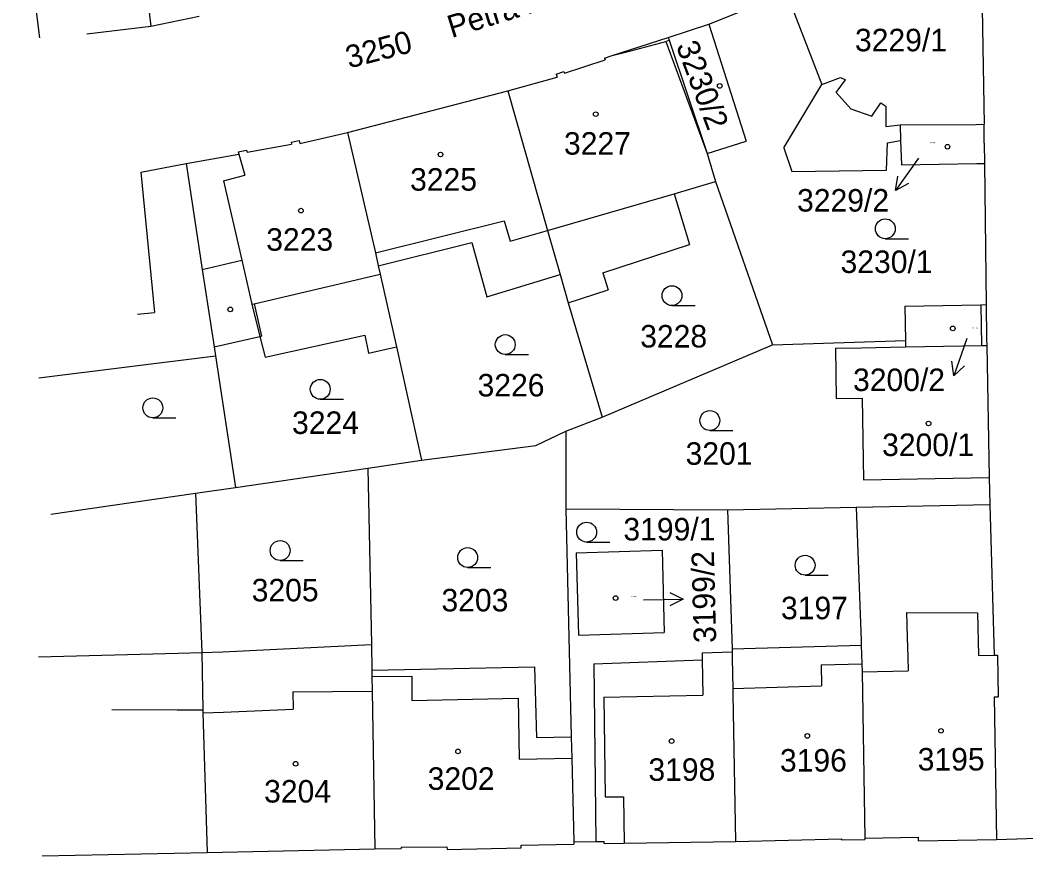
# Model space of a CAD drawing. Extents: x -735092 to -733385, y -1122435 to -1118992.
# Drawn here: x -734521.9 to -734445.9, y -1120334.2 to -1120271.1 of the extents above; entities that cross this region are included whole.
import ezdxf

# ---------------------------------------------------------------- set-up
doc = ezdxf.new("R2010")
doc.units = 0
for name, color, linetype in [('Vrstva 1', 7, 'Continuous'), ('Vrstva 15', 7, 'Continuous'), ('Vrstva 16', 7, 'Continuous'), ('Vrstva 18', 7, 'Continuous'), ('Vrstva 19', 7, 'Continuous'), ('Vrstva 25', 7, 'Continuous'), ('Vrstva 4', 7, 'Continuous')]:
    doc.layers.add(name, color=color, linetype=linetype)

msp = doc.modelspace()

# ---------------------------------------------------------------- linework, layer by layer
at = {"layer": 'Vrstva 1'}
for points in [[(-734521.87, -1120260.86), (-734520.4, -1120272.42)], [(-734449.23, -1120267.25), (-734449.01, -1120278.95)], [(-734469.82, -1120271.38), (-734463.95, -1120269.02)], [(-734463.95, -1120269.02), (-734461.29, -1120275.96)], [(-734512, -1120271.55), (-734508.33, -1120270.79)], [(-734516.84, -1120272.13), (-734512, -1120271.55)], [(-734472.9, -1120272.39), (-734469.82, -1120271.38)], [(-734469.82, -1120271.38), (-734467, -1120280.22)], [(-734473.07, -1120272.7), (-734472.83, -1120272.6)], [(-734472.9, -1120272.39), (-734472.83, -1120272.6)], [(-734477.13, -1120273.77), (-734475.73, -1120273.4)], [(-734475.73, -1120273.4), (-734473.07, -1120272.7)], [(-734473.07, -1120272.7), (-734469.95, -1120281.15)], [(-734480.73, -1120275.09), (-734477.67, -1120274.08)], [(-734477.71, -1120273.96), (-734477.13, -1120273.77)], [(-734477.71, -1120273.96), (-734477.67, -1120274.08)], [(-734485.01, -1120276.44), (-734481.29, -1120275.4)], [(-734481.37, -1120275.17), (-734480.77, -1120274.97)], [(-734481.37, -1120275.17), (-734481.29, -1120275.4)], [(-734480.77, -1120274.97), (-734480.73, -1120275.09)], [(-734497.12, -1120279.58), (-734485.01, -1120276.44)], [(-734485.01, -1120276.44), (-734482.01, -1120286.98)], [(-734464.16, -1120280.73), (-734461.29, -1120275.96)], [(-734455.37, -1120279), (-734449.62, -1120278.98)], [(-734455.37, -1120279), (-734455.33, -1120280.18)], [(-734449.62, -1120278.98), (-734449.01, -1120278.95)], [(-734449.01, -1120280.37), (-734449.01, -1120278.95)], [(-734501.39, -1120280.3), (-734500.77, -1120280.19)], [(-734500.77, -1120280.19), (-734500.73, -1120280.4)], [(-734500.73, -1120280.4), (-734497.12, -1120279.58)], [(-734497.12, -1120279.58), (-734495.02, -1120288.66)], [(-734469.95, -1120281.15), (-734467, -1120280.22)], [(-734456.33, -1120280.36), (-734455.33, -1120280.18)], [(-734455.33, -1120280.18), (-734455.27, -1120282.03)], [(-734505.38, -1120281.04), (-734504.75, -1120280.92)], [(-734504.75, -1120280.92), (-734504.72, -1120281.05)], [(-734504.72, -1120281.05), (-734501.36, -1120280.46)], [(-734501.39, -1120280.3), (-734501.36, -1120280.46)], [(-734464.16, -1120280.73), (-734463.55, -1120282.52)], [(-734456.39, -1120282.43), (-734456.33, -1120280.36)], [(-734449.01, -1120280.37), (-734449, -1120281.92)], [(-734509.31, -1120281.93), (-734505.35, -1120281.21)], [(-734505.38, -1120281.04), (-734505.35, -1120281.21)], [(-734505.35, -1120281.21), (-734504.9, -1120282.81)], [(-734469.95, -1120281.15), (-734469.33, -1120283.29)], [(-734512.75, -1120282.57), (-734509.31, -1120281.93)], [(-734509.31, -1120281.93), (-734508.1, -1120289.92)], [(-734463.55, -1120282.52), (-734456.39, -1120282.43)], [(-734455.27, -1120282.03), (-734449.58, -1120281.93)], [(-734449.58, -1120281.93), (-734449, -1120281.92)], [(-734449, -1120281.92), (-734448.86, -1120292.58)], [(-734506.49, -1120283.24), (-734504.9, -1120282.81)], [(-734506.49, -1120283.24), (-734505.12, -1120289.23)], [(-734472.44, -1120284.21), (-734469.33, -1120283.29)], [(-734469.33, -1120283.29), (-734465.02, -1120295.62)], [(-734472.44, -1120284.21), (-734471.28, -1120288.03)], [(-734482.01, -1120286.98), (-734481.06, -1120290.31)], [(-734494.8, -1120289.64), (-734487.74, -1120287.88)], [(-734487.74, -1120287.88), (-734486.6, -1120292)], [(-734477.84, -1120290.19), (-734471.28, -1120288.03)], [(-734505.12, -1120289.23), (-734504.36, -1120292.55)], [(-734495.02, -1120288.66), (-734494.8, -1120289.64)], [(-734508.1, -1120289.92), (-734507.21, -1120295.77)], [(-734494.8, -1120289.64), (-734494.65, -1120290.27)], [(-734494.65, -1120290.27), (-734493.43, -1120295.76)], [(-734486.6, -1120292), (-734481.06, -1120290.31)], [(-734481.06, -1120290.31), (-734480.45, -1120292.44)], [(-734477.84, -1120290.19), (-734477.43, -1120291.46)], [(-734480.45, -1120292.44), (-734477.43, -1120291.46)], [(-734504.36, -1120292.55), (-734503.75, -1120294.99)], [(-734480.45, -1120292.44), (-734477.88, -1120301.09)], [(-734455.02, -1120292.69), (-734449.26, -1120292.59)], [(-734455.02, -1120292.69), (-734454.97, -1120295.28)], [(-734449.26, -1120292.59), (-734448.86, -1120292.58)], [(-734448.86, -1120292.58), (-734448.83, -1120295.17)], [(-734503.75, -1120294.99), (-734503.36, -1120296.56)], [(-734503.36, -1120296.56), (-734495.81, -1120294.89)], [(-734495.81, -1120294.89), (-734495.54, -1120296.26)], [(-734465.02, -1120295.62), (-734454.97, -1120295.28)], [(-734454.97, -1120295.28), (-734454.96, -1120295.78)], [(-734448.83, -1120295.17), (-734448.82, -1120295.67)], [(-734507.21, -1120295.77), (-734507.1, -1120296.46)], [(-734495.54, -1120296.26), (-734493.43, -1120295.76)], [(-734493.43, -1120295.76), (-734491.53, -1120304.33)], [(-734477.88, -1120301.09), (-734465.02, -1120295.62)], [(-734460.26, -1120295.88), (-734458.31, -1120295.84)], [(-734460.26, -1120295.88), (-734460.19, -1120299.68)], [(-734458.31, -1120295.84), (-734454.96, -1120295.78)], [(-734454.96, -1120295.78), (-734449.22, -1120295.68)], [(-734449.22, -1120295.68), (-734448.82, -1120295.67)], [(-734448.82, -1120295.67), (-734448.64, -1120305.65)], [(-734520.46, -1120298.1), (-734507.1, -1120296.46)], [(-734507.1, -1120296.46), (-734505.59, -1120306.39)], [(-734460.19, -1120299.68), (-734458.24, -1120299.64)], [(-734458.24, -1120299.64), (-734458.14, -1120305.82)], [(-734480.64, -1120302.15), (-734477.88, -1120301.09)], [(-734482.89, -1120303.22), (-734480.64, -1120302.15)], [(-734480.64, -1120302.15), (-734480.62, -1120308.01)], [(-734491.53, -1120304.33), (-734482.89, -1120303.22)], [(-734495.6, -1120304.94), (-734491.53, -1120304.33)], [(-734505.59, -1120306.39), (-734495.6, -1120304.94)], [(-734495.6, -1120304.94), (-734495.32, -1120318.25)], [(-734458.14, -1120305.82), (-734448.64, -1120305.65)], [(-734448.64, -1120305.65), (-734448.6, -1120307.68)], [(-734519.55, -1120308.42), (-734508.61, -1120306.83)], [(-734508.61, -1120306.83), (-734505.59, -1120306.39)], [(-734508.61, -1120306.83), (-734508.13, -1120318.86)], [(-734480.62, -1120308.01), (-734468.42, -1120308.09)], [(-734480.62, -1120308.01), (-734480.22, -1120325.24)], [(-734468.42, -1120308.09), (-734458.69, -1120307.89)], [(-734468.42, -1120308.09), (-734468.07, -1120318.59)], [(-734458.69, -1120307.89), (-734448.6, -1120307.68)], [(-734458.69, -1120307.89), (-734458.31, -1120317.99)], [(-734448.6, -1120307.68), (-734448.25, -1120319.07)], [(-734479.86, -1120311.33), (-734473.34, -1120311.13)], [(-734479.86, -1120311.33), (-734479.67, -1120317.55)], [(-734473.34, -1120311.13), (-734473.21, -1120317.35)], [(-734479.67, -1120317.55), (-734473.21, -1120317.35)], [(-734506.56, -1120318.82), (-734495.32, -1120318.25)], [(-734495.32, -1120318.25), (-734495.3, -1120320.21)], [(-734458.31, -1120317.99), (-734458.3, -1120318.32)], [(-734520.49, -1120319.18), (-734509.92, -1120318.91)], [(-734509.92, -1120318.91), (-734508.13, -1120318.86)], [(-734508.13, -1120318.86), (-734506.56, -1120318.82)], [(-734508.13, -1120318.86), (-734508.07, -1120323.2)], [(-734470.34, -1120318.88), (-734468.07, -1120318.82)], [(-734470.34, -1120318.88), (-734470.33, -1120319.41)], [(-734468.07, -1120318.59), (-734458.3, -1120318.32)], [(-734468.07, -1120318.59), (-734468.07, -1120318.82)], [(-734468.07, -1120318.82), (-734468.05, -1120319.32)], [(-734458.3, -1120318.32), (-734458.25, -1120319.71)], [(-734478.51, -1120319.72), (-734470.33, -1120319.41)], [(-734478.51, -1120319.72), (-734478.37, -1120333.15)], [(-734468.05, -1120319.32), (-734468.01, -1120321.58)], [(-734458.25, -1120319.71), (-734458.24, -1120320.32)], [(-734448.25, -1120319.07), (-734448.02, -1120319.07)], [(-734448.02, -1120319.07), (-734447.97, -1120322.22)], [(-734495.3, -1120320.21), (-734482.99, -1120319.95)], [(-734495.3, -1120320.21), (-734495.29, -1120320.67)], [(-734482.99, -1120319.95), (-734482.85, -1120325.29)], [(-734458.24, -1120320.32), (-734458.03, -1120332.9)], [(-734495.29, -1120320.67), (-734495.27, -1120321.79)], [(-734495.27, -1120321.79), (-734495.07, -1120333.71)], [(-734468.01, -1120321.58), (-734468, -1120322.01)], [(-734468, -1120322.01), (-734467.82, -1120333.15)], [(-734448.27, -1120322.22), (-734448.08, -1120333)], [(-734448.27, -1120322.22), (-734447.97, -1120322.22)], [(-734508.07, -1120323.2), (-734508.06, -1120323.43)], [(-734508.06, -1120323.43), (-734507.74, -1120333.98)], [(-734482.85, -1120325.29), (-734480.22, -1120325.24)], [(-734480.22, -1120325.24), (-734480.18, -1120326.84)], [(-734480.18, -1120326.84), (-734480.03, -1120333.18)], [(-734448.08, -1120333), (-734432.8, -1120332.49)], [(-734484.01, -1120333.43), (-734480.03, -1120333.34)], [(-734484.01, -1120333.61), (-734484.01, -1120333.43)], [(-734480.03, -1120333.18), (-734478.37, -1120333.15)], [(-734480.03, -1120333.18), (-734480.03, -1120333.34)], [(-734478.37, -1120333.15), (-734477.73, -1120333.14)], [(-734477.73, -1120333.3), (-734477.73, -1120333.14)], [(-734477.73, -1120333.3), (-734476.22, -1120333.28)], [(-734476.22, -1120333.28), (-734467.82, -1120333.15)], [(-734467.82, -1120333.15), (-734459.81, -1120332.93)], [(-734459.81, -1120332.93), (-734459.81, -1120333.03)], [(-734459.81, -1120333.03), (-734458.03, -1120333)], [(-734458.03, -1120332.9), (-734453.97, -1120332.81)], [(-734458.03, -1120332.9), (-734458.03, -1120333)], [(-734453.97, -1120333.1), (-734453.97, -1120332.81)], [(-734453.97, -1120333.1), (-734448.08, -1120333)], [(-734520.2, -1120334.23), (-734507.74, -1120333.98)], [(-734507.74, -1120333.98), (-734495.07, -1120333.71)], [(-734495.07, -1120333.71), (-734493.08, -1120333.67)], [(-734493.08, -1120333.57), (-734489.62, -1120333.54)], [(-734493.08, -1120333.57), (-734493.08, -1120333.67)], [(-734489.62, -1120333.54), (-734489.61, -1120333.74)], [(-734489.61, -1120333.74), (-734484.01, -1120333.61)]]:
    msp.add_lwpolyline(points, dxfattribs=at)
at = {"layer": 'Vrstva 25'}
for points in [[(-734453.99, -1120281.52), (-734455.723, -1120283.968)], [(-734454.737, -1120283.441), (-734455.723, -1120283.968), (-734455.553, -1120282.863)], [(-734456.49, -1120287.6), (-734454.74, -1120287.6)], [(-734472.61, -1120292.65), (-734470.86, -1120292.65)], [(-734450.33, -1120295.14), (-734451.316, -1120297.973)], [(-734485.21, -1120296.35), (-734483.46, -1120296.35)], [(-734450.515, -1120297.193), (-734451.316, -1120297.973), (-734451.459, -1120296.864)], [(-734499.19, -1120299.73), (-734497.44, -1120299.73)], [(-734511.84, -1120301.13), (-734510.09, -1120301.13)], [(-734469.75, -1120302.09), (-734468, -1120302.09)], [(-734479.06, -1120310.52), (-734477.31, -1120310.52)], [(-734502.22, -1120311.91), (-734500.47, -1120311.91)], [(-734488.05, -1120312.44), (-734486.3, -1120312.44)], [(-734462.55, -1120313.02), (-734460.8, -1120313.02)], [(-734472.78, -1120314.342), (-734471.771, -1120314.823), (-734472.761, -1120315.341)], [(-734474.77, -1120314.88), (-734471.771, -1120314.823)]]:
    msp.add_lwpolyline(points, dxfattribs=at)
for centre, radius in [((-734469, -1120276.06), 0.175), ((-734478.37, -1120278.19), 0.175), ((-734451.79, -1120280.65), 0.174), ((-734490.1, -1120281.24), 0.175), ((-734500.65, -1120285.48), 0.175), ((-734456.49, -1120286.85), 0.75), ((-734472.61, -1120291.9), 0.75), ((-734505.99, -1120292.94), 0.175), ((-734451.39, -1120294.38), 0.175), ((-734485.21, -1120295.6), 0.75), ((-734499.19, -1120298.98), 0.75), ((-734511.84, -1120300.38), 0.75), ((-734469.75, -1120301.34), 0.75), ((-734453.22, -1120301.56), 0.175), ((-734479.06, -1120309.77), 0.75), ((-734502.22, -1120311.16), 0.75), ((-734488.05, -1120311.69), 0.75), ((-734462.55, -1120312.27), 0.75), ((-734476.87, -1120314.75), 0.175), ((-734462.38, -1120325.17), 0.175), ((-734452.28, -1120324.78), 0.175), ((-734472.64, -1120325.56), 0.175), ((-734488.78, -1120326.34), 0.175), ((-734501.05, -1120327.27), 0.175)]:
    msp.add_circle(centre, radius, dxfattribs=at)
at = {"layer": 'Vrstva 4'}
for points in [[(-734512.4, -1120268.2), (-734512, -1120271.55)], [(-734477.13, -1120273.77), (-734472.9, -1120272.39)], [(-734472.83, -1120272.6), (-734469.95, -1120281.15)], [(-734461.29, -1120275.96), (-734459.88, -1120275.42)], [(-734460.19, -1120276.55), (-734459.49, -1120275.59)], [(-734459.88, -1120275.42), (-734459.49, -1120275.59)], [(-734460.19, -1120276.55), (-734459.09, -1120277.8)], [(-734459.09, -1120277.8), (-734457.5, -1120278.33)], [(-734457.5, -1120278.33), (-734456.83, -1120277.33)], [(-734456.83, -1120277.33), (-734456.45, -1120277.59)], [(-734456.45, -1120277.59), (-734456.44, -1120279.11)], [(-734456.44, -1120279.11), (-734455.37, -1120279)], [(-734512.75, -1120282.57), (-734511.72, -1120293.18)], [(-734482.01, -1120286.98), (-734472.44, -1120284.21)], [(-734495.02, -1120288.66), (-734485.28, -1120286.24)], [(-734485.28, -1120286.24), (-734484.83, -1120287.79)], [(-734484.83, -1120287.79), (-734482.01, -1120286.98)], [(-734508.1, -1120289.92), (-734505.12, -1120289.23)], [(-734504.19, -1120292.51), (-734494.65, -1120290.27)], [(-734504.36, -1120292.55), (-734504.19, -1120292.51)], [(-734504.19, -1120292.51), (-734503.63, -1120294.96)], [(-734449.26, -1120292.59), (-734449.22, -1120295.68)], [(-734513.01, -1120293.3), (-734511.72, -1120293.18)], [(-734507.21, -1120295.77), (-734503.75, -1120294.99)], [(-734503.75, -1120294.99), (-734503.63, -1120294.96)], [(-734454.88, -1120315.84), (-734454.83, -1120317.72)], [(-734454.88, -1120315.84), (-734449.53, -1120315.86)], [(-734449.53, -1120315.86), (-734449.44, -1120319.1)], [(-734454.83, -1120317.72), (-734454.79, -1120319.19)], [(-734470.33, -1120319.41), (-734470.28, -1120322.09)], [(-734461.34, -1120319.79), (-734458.25, -1120319.71)], [(-734454.79, -1120319.19), (-734454.76, -1120320.25)], [(-734449.44, -1120319.1), (-734448.25, -1120319.07)], [(-734461.34, -1120319.79), (-734461.3, -1120321.39)], [(-734458.24, -1120320.32), (-734454.76, -1120320.25)], [(-734495.29, -1120320.67), (-734492.28, -1120320.65)], [(-734492.28, -1120320.65), (-734492.27, -1120322.5)], [(-734501.25, -1120321.83), (-734495.27, -1120321.79)], [(-734501.25, -1120321.83), (-734501.24, -1120323.14)], [(-734468.01, -1120321.58), (-734461.3, -1120321.39)], [(-734492.27, -1120322.5), (-734484.24, -1120322.32)], [(-734484.24, -1120322.32), (-734484.15, -1120326.92)], [(-734477.76, -1120322.24), (-734470.28, -1120322.09)], [(-734477.76, -1120322.24), (-734477.67, -1120329.78)], [(-734514.93, -1120323.17), (-734510.01, -1120323.19)], [(-734510.01, -1120323.19), (-734508.07, -1120323.2)], [(-734508.06, -1120323.43), (-734506.49, -1120323.36)], [(-734506.49, -1120323.36), (-734501.24, -1120323.14)], [(-734484.15, -1120326.92), (-734480.18, -1120326.84)], [(-734477.67, -1120329.78), (-734476.28, -1120329.77)], [(-734476.28, -1120329.77), (-734476.22, -1120333.28)]]:
    msp.add_lwpolyline(points, dxfattribs=at)

# ---------------------------------------------------------------- texts
at = {"layer": 'Vrstva 15'}
msp.add_text('Petra z Ústí', height=1.69999, rotation=17.30014, dxfattribs=at).set_placement((-734489.259, -1120272.45))
at = {"layer": 'Vrstva 16'}
for s, p in [('3229/2', (-734463.157, -1120285.55)), ('3200/2', (-734458.927, -1120299.11))]:
    msp.add_text(s, height=1.7, dxfattribs=at).set_placement(p)
msp.add_text('3199/2', height=1.7, rotation=91.50073, dxfattribs=at).set_placement((-734469.262, -1120318.122))
at = {"layer": 'Vrstva 18'}
msp.add_text('3250', height=1.7, rotation=14.50012, dxfattribs=at).set_placement((-734497.017, -1120274.747))
for s, p in [('3230/1', (-734459.87, -1120290.19)), ('3228', (-734475.01, -1120295.82)), ('3226', (-734487.3, -1120299.52)), ('3224', (-734501.32, -1120302.35)), ('3201', (-734471.58, -1120304.68)), ('3199/1', (-734476.28, -1120310.4)), ('3205', (-734504.37, -1120315)), ('3203', (-734490.03, -1120315.76)), ('3197', (-734464.37, -1120316.35))]:
    msp.add_text(s, height=1.7, dxfattribs=at).set_placement(p)
at = {"layer": 'Vrstva 19'}
for s, height, p in [('3229/1', 1.7, (-734458.78, -1120273.44)), ('3227', 1.7, (-734480.77, -1120281.25)), ('3229/2', 0.1, (-734453.13, -1120280.4)), ('3225', 1.7, (-734492.4, -1120283.97)), ('3223', 1.7, (-734503.27, -1120288.51)), ('3200/2', 0.1, (-734449.93, -1120294.36)), ('3200/1', 1.7, (-734456.73, -1120304.02)), ('3199/2', 0.1, (-734475.72, -1120314.7)), ('3196', 1.7, (-734464.45, -1120327.86)), ('3195', 1.7, (-734454.04, -1120327.78)), ('3198', 1.7, (-734474.39, -1120328.56)), ('3202', 1.7, (-734491.07, -1120329.24)), ('3204', 1.7, (-734503.43, -1120330.2))]:
    msp.add_text(s, height=height, dxfattribs=at).set_placement(p)
msp.add_text('3230/2', height=1.7, rotation=290.60231, dxfattribs=at).set_placement((-734472.323, -1120273.016))

doc.saveas('drawing.dxf')
